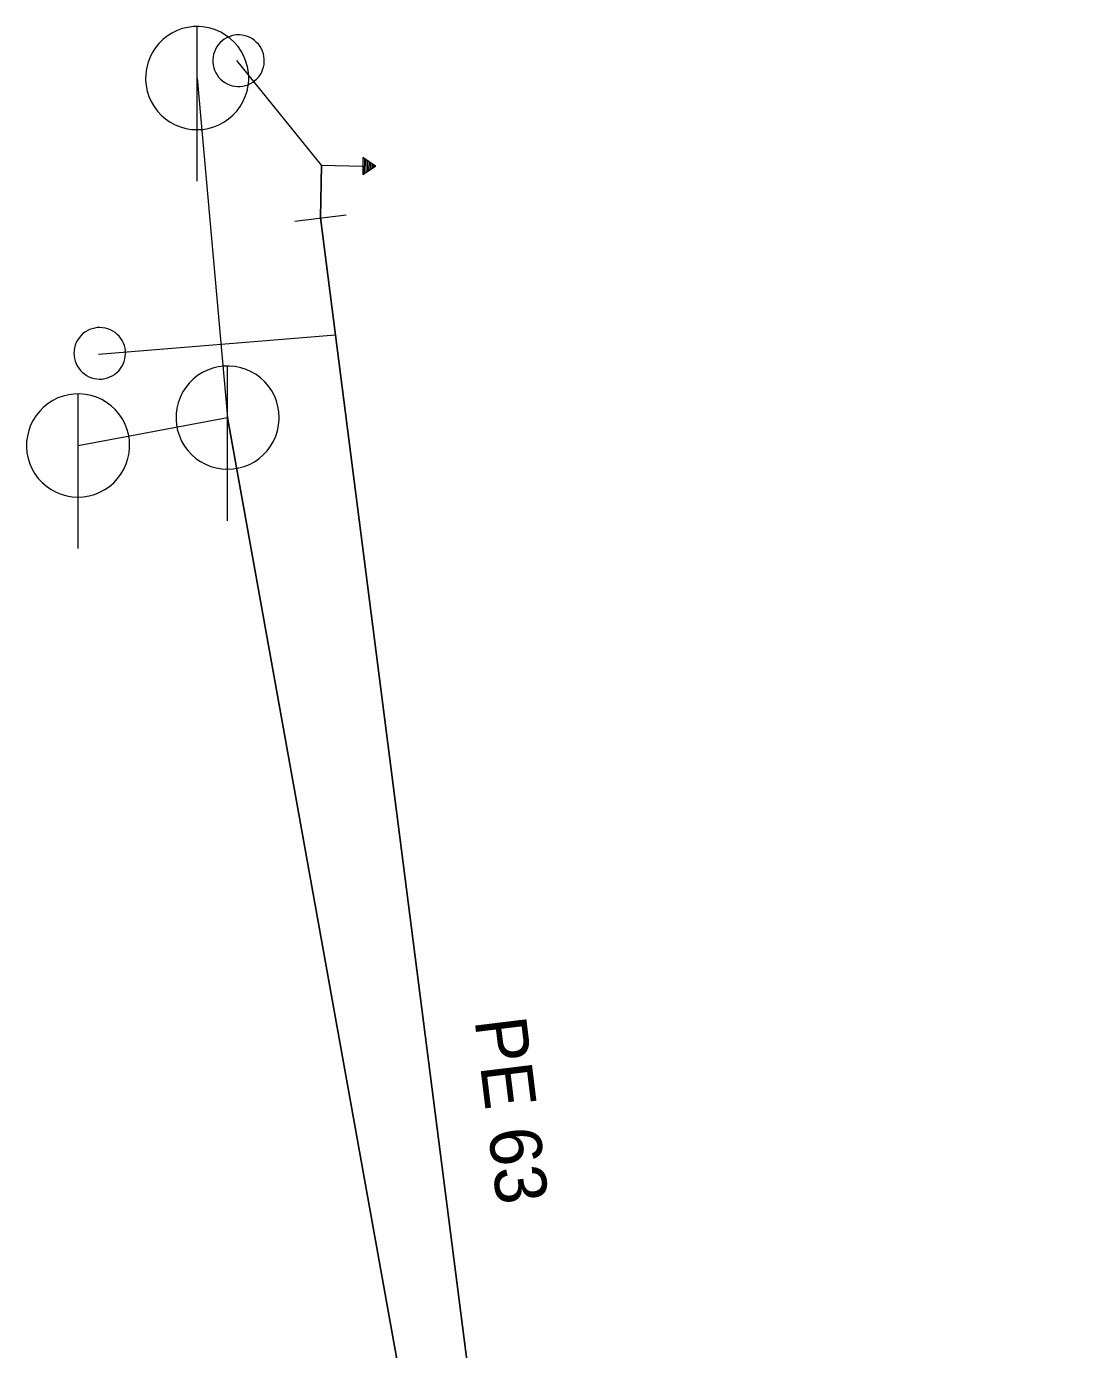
# Model space of a CAD drawing. Extents: x -779496 to -779026, y -977086 to -976624.
# Drawn here: x -779174.9 to -779154.74, y -976726.5 to -976700.86 of the extents above; entities that cross this region are included whole.
import ezdxf

# ---------------------------------------------------------------- set-up
doc = ezdxf.new("R2010")
doc.units = 0
doc.header["$LTSCALE"] = 0.4
doc.linetypes.add('MEDIUM_DASHED', pattern=[4.5, 3, -1.5])
for name, color, linetype, lineweight in [('1', 7, 'MEDIUM_DASHED', 25), ('11', 7, 'Continuous', 13), ('13', 7, 'Continuous', 13), ('14', 7, 'Continuous', 13), ('17', 7, 'Continuous', 25), ('22', 7, 'Continuous', 13), ('23', 7, 'Continuous', 13), ('34', 7, 'Continuous', 13)]:
    doc.layers.add(name, color=color, linetype=linetype, lineweight=lineweight)

msp = doc.modelspace()

# ---------------------------------------------------------------- linework, layer by layer
at = {"layer": '11'}
for p in [(-779171.59, -976701.859), (-779173.899, -976708.98)]:
    msp.add_line(p, (-779171, -976708.44), dxfattribs=at)
at = {"layer": '13'}
for p, q in [((-779169.18, -976703.55), (-779170.82, -976701.52)), ((-779168.91, -976706.84), (-779173.5, -976707.219))]:
    msp.add_line(p, q, dxfattribs=at)
at = {"layer": '14', "lineweight": 25}
msp.add_line((-779171, -976708.44), (-779163.01, -976752.87), dxfattribs=at)
at = {"layer": '17'}
msp.add_lwpolyline([(-779154.739, -976751.5), (-779164.55, -976740.87), (-779168.91, -976706.84), (-779169.199, -976704.57), (-779169.18, -976703.55)], dxfattribs=at)
at = {"layer": '22'}
for p, q in [((-779171.59, -976703.859), (-779171.589, -976700.859)), ((-779171, -976710.44), (-779170.999, -976707.44)), ((-779173.899, -976710.98), (-779173.898, -976707.98))]:
    msp.add_line(p, q, dxfattribs=at)
for points in [[(-779170.59, -976701.859), (-779170.595, -976701.75), (-779170.613, -976701.642), (-779170.643, -976701.536), (-779170.683, -976701.435), (-779170.735, -976701.338), (-779170.797, -976701.248), (-779170.869, -976701.165), (-779170.949, -976701.091), (-779171.037, -976701.025), (-779171.131, -976700.97), (-779171.231, -976700.925), (-779171.336, -976700.892), (-779171.443, -976700.87), (-779171.552, -976700.86), (-779171.662, -976700.862), (-779171.77, -976700.876), (-779171.877, -976700.901), (-779171.98, -976700.938), (-779172.078, -976700.987), (-779172.17, -976701.045), (-779172.256, -976701.114), (-779172.333, -976701.191), (-779172.402, -976701.277), (-779172.461, -976701.369), (-779172.509, -976701.467), (-779172.546, -976701.57), (-779172.572, -976701.677), (-779172.586, -976701.785), (-779172.589, -976701.895), (-779172.579, -976702.004), (-779172.558, -976702.111), (-779172.524, -976702.215), (-779172.48, -976702.315), (-779172.425, -976702.41), (-779172.359, -976702.498), (-779172.285, -976702.578), (-779172.202, -976702.65), (-779172.112, -976702.712), (-779172.016, -976702.764), (-779171.914, -976702.805), (-779171.809, -976702.835), (-779171.701, -976702.853), (-779171.591, -976702.859), (-779171.482, -976702.853), (-779171.374, -976702.835), (-779171.269, -976702.806), (-779171.167, -976702.765), (-779171.07, -976702.713), (-779170.98, -976702.651), (-779170.897, -976702.58), (-779170.822, -976702.5), (-779170.757, -976702.412), (-779170.701, -976702.318), (-779170.657, -976702.218), (-779170.623, -976702.114), (-779170.601, -976702.006), (-779170.591, -976701.897)], [(-779170, -976708.44), (-779170.005, -976708.331), (-779170.023, -976708.223), (-779170.053, -976708.117), (-779170.093, -976708.016), (-779170.145, -976707.919), (-779170.207, -976707.829), (-779170.279, -976707.746), (-779170.359, -976707.672), (-779170.447, -976707.606), (-779170.541, -976707.551), (-779170.641, -976707.506), (-779170.746, -976707.473), (-779170.853, -976707.451), (-779170.962, -976707.441), (-779171.072, -976707.443), (-779171.18, -976707.457), (-779171.287, -976707.482), (-779171.39, -976707.519), (-779171.488, -976707.568), (-779171.58, -976707.626), (-779171.666, -976707.695), (-779171.743, -976707.772), (-779171.812, -976707.858), (-779171.871, -976707.95), (-779171.919, -976708.048), (-779171.956, -976708.151), (-779171.982, -976708.258), (-779171.996, -976708.366), (-779171.999, -976708.476), (-779171.989, -976708.585), (-779171.968, -976708.692), (-779171.934, -976708.796), (-779171.89, -976708.896), (-779171.835, -976708.991), (-779171.769, -976709.079), (-779171.695, -976709.159), (-779171.612, -976709.231), (-779171.522, -976709.293), (-779171.426, -976709.345), (-779171.324, -976709.386), (-779171.219, -976709.416), (-779171.111, -976709.434), (-779171.001, -976709.44), (-779170.892, -976709.434), (-779170.784, -976709.416), (-779170.679, -976709.387), (-779170.577, -976709.346), (-779170.48, -976709.294), (-779170.39, -976709.232), (-779170.307, -976709.161), (-779170.232, -976709.081), (-779170.167, -976708.993), (-779170.111, -976708.899), (-779170.067, -976708.799), (-779170.033, -976708.695), (-779170.011, -976708.587), (-779170.001, -976708.478)], [(-779172.899, -976708.98), (-779172.904, -976708.871), (-779172.922, -976708.763), (-779172.952, -976708.657), (-779172.992, -976708.556), (-779173.044, -976708.459), (-779173.106, -976708.369), (-779173.178, -976708.286), (-779173.258, -976708.212), (-779173.346, -976708.146), (-779173.44, -976708.091), (-779173.54, -976708.046), (-779173.645, -976708.013), (-779173.752, -976707.991), (-779173.861, -976707.981), (-779173.971, -976707.983), (-779174.079, -976707.997), (-779174.186, -976708.022), (-779174.289, -976708.059), (-779174.387, -976708.108), (-779174.479, -976708.166), (-779174.565, -976708.235), (-779174.642, -976708.312), (-779174.711, -976708.398), (-779174.77, -976708.49), (-779174.818, -976708.588), (-779174.855, -976708.691), (-779174.881, -976708.798), (-779174.895, -976708.906), (-779174.898, -976709.016), (-779174.888, -976709.125), (-779174.867, -976709.232), (-779174.833, -976709.336), (-779174.789, -976709.436), (-779174.734, -976709.531), (-779174.668, -976709.619), (-779174.594, -976709.699), (-779174.511, -976709.771), (-779174.421, -976709.833), (-779174.325, -976709.885), (-779174.223, -976709.926), (-779174.118, -976709.956), (-779174.01, -976709.974), (-779173.9, -976709.98), (-779173.791, -976709.974), (-779173.683, -976709.956), (-779173.578, -976709.927), (-779173.476, -976709.886), (-779173.379, -976709.834), (-779173.289, -976709.772), (-779173.206, -976709.701), (-779173.131, -976709.621), (-779173.066, -976709.533), (-779173.01, -976709.439), (-779172.966, -976709.339), (-779172.932, -976709.235), (-779172.91, -976709.127), (-779172.9, -976709.018)]]:
    msp.add_lwpolyline(points, close=True, dxfattribs=at)
at = {"layer": '23'}
for points in [[(-779170.289, -976701.492), (-779170.294, -976701.441), (-779170.306, -976701.389), (-779170.321, -976701.34), (-779170.345, -976701.292), (-779170.371, -976701.247), (-779170.402, -976701.205), (-779170.438, -976701.167), (-779170.476, -976701.132), (-779170.519, -976701.101), (-779170.565, -976701.076), (-779170.613, -976701.055), (-779170.662, -976701.039), (-779170.714, -976701.03), (-779170.766, -976701.024), (-779170.818, -976701.024), (-779170.871, -976701.03), (-779170.922, -976701.042), (-779170.971, -976701.059), (-779171.019, -976701.081), (-779171.063, -976701.107), (-779171.106, -976701.137), (-779171.145, -976701.173), (-779171.18, -976701.213), (-779171.208, -976701.255), (-779171.235, -976701.301), (-779171.255, -976701.348), (-779171.271, -976701.399), (-779171.281, -976701.45), (-779171.286, -976701.502), (-779171.286, -976701.554), (-779171.28, -976701.606), (-779171.269, -976701.658), (-779171.252, -976701.708), (-779171.23, -976701.755), (-779171.204, -976701.799), (-779171.173, -976701.841), (-779171.136, -976701.881), (-779171.099, -976701.915), (-779171.054, -976701.946)], [(-779171.106, -976701.137), (-779171.145, -976701.173), (-779171.18, -976701.213), (-779171.208, -976701.255), (-779171.235, -976701.301), (-779171.255, -976701.348), (-779171.271, -976701.399), (-779171.281, -976701.45), (-779171.286, -976701.502), (-779171.286, -976701.554), (-779171.28, -976701.606), (-779171.269, -976701.658), (-779171.252, -976701.708), (-779171.23, -976701.755), (-779171.204, -976701.799), (-779171.173, -976701.841), (-779171.136, -976701.881), (-779171.099, -976701.915), (-779171.054, -976701.946), (-779171.011, -976701.971), (-779170.963, -976701.992), (-779170.911, -976702.007), (-779170.86, -976702.018), (-779170.807, -976702.022), (-779170.755, -976702.023), (-779170.704, -976702.016), (-779170.652, -976702.004), (-779170.604, -976701.988), (-779170.556, -976701.966), (-779170.511, -976701.939), (-779170.469, -976701.908), (-779170.43, -976701.873), (-779170.395, -976701.834), (-779170.364, -976701.791), (-779170.339, -976701.746), (-779170.32, -976701.698), (-779170.304, -976701.648), (-779170.293, -976701.596), (-779170.288, -976701.544), (-779170.289, -976701.492)], [(-779170.971, -976701.059), (-779171.019, -976701.081), (-779171.063, -976701.107), (-779171.106, -976701.137)], [(-779171.054, -976701.946), (-779171.011, -976701.971), (-779170.963, -976701.992), (-779170.911, -976702.007), (-779170.86, -976702.018), (-779170.807, -976702.022), (-779170.755, -976702.023), (-779170.704, -976702.016), (-779170.652, -976702.004), (-779170.604, -976701.988), (-779170.556, -976701.966), (-779170.511, -976701.939), (-779170.469, -976701.908), (-779170.43, -976701.873), (-779170.395, -976701.834), (-779170.364, -976701.791), (-779170.339, -976701.746), (-779170.32, -976701.698), (-779170.304, -976701.648), (-779170.293, -976701.596), (-779170.288, -976701.544), (-779170.289, -976701.492), (-779170.294, -976701.441), (-779170.306, -976701.389), (-779170.321, -976701.34), (-779170.345, -976701.292), (-779170.371, -976701.247), (-779170.402, -976701.205), (-779170.438, -976701.167), (-779170.476, -976701.132), (-779170.519, -976701.101), (-779170.565, -976701.076), (-779170.613, -976701.055), (-779170.662, -976701.039), (-779170.714, -976701.03), (-779170.766, -976701.024), (-779170.818, -976701.024), (-779170.871, -976701.03), (-779170.922, -976701.042), (-779170.971, -976701.059)], [(-779173.224, -976706.764), (-779173.269, -976706.739), (-779173.319, -976706.72), (-779173.368, -976706.705), (-779173.421, -976706.698), (-779173.473, -976706.695), (-779173.525, -976706.696), (-779173.576, -976706.705), (-779173.627, -976706.717), (-779173.677, -976706.735), (-779173.723, -976706.759), (-779173.768, -976706.787), (-779173.809, -976706.818), (-779173.846, -976706.856), (-779173.879, -976706.895), (-779173.908, -976706.939), (-779173.933, -976706.986), (-779173.952, -976707.035), (-779173.966, -976707.085), (-779173.974, -976707.137), (-779173.978, -976707.188), (-779173.976, -976707.24), (-779173.969, -976707.293), (-779173.956, -976707.344), (-779173.937, -976707.392), (-779173.914, -976707.439), (-779173.886, -976707.483), (-779173.852, -976707.524), (-779173.816, -976707.561), (-779173.776, -976707.594), (-779173.733, -976707.624), (-779173.687, -976707.648), (-779173.638, -976707.668), (-779173.587, -976707.682), (-779173.536, -976707.691), (-779173.484, -976707.693), (-779173.432, -976707.692), (-779173.379, -976707.684), (-779173.33, -976707.672), (-779173.279, -976707.652)], [(-779173.976, -976707.24), (-779173.969, -976707.293), (-779173.956, -976707.344), (-779173.937, -976707.392), (-779173.914, -976707.439), (-779173.886, -976707.483), (-779173.852, -976707.524), (-779173.816, -976707.561), (-779173.776, -976707.594), (-779173.733, -976707.624), (-779173.687, -976707.648), (-779173.638, -976707.668), (-779173.587, -976707.682), (-779173.536, -976707.691), (-779173.484, -976707.693), (-779173.432, -976707.692), (-779173.379, -976707.684), (-779173.33, -976707.672), (-779173.279, -976707.652), (-779173.234, -976707.63), (-779173.189, -976707.603), (-779173.147, -976707.568), (-779173.11, -976707.532), (-779173.077, -976707.491), (-779173.047, -976707.448), (-779173.024, -976707.402), (-779173.005, -976707.353), (-779172.991, -976707.303), (-779172.982, -976707.251), (-779172.979, -976707.199), (-779172.981, -976707.147), (-779172.988, -976707.095), (-779173.001, -976707.044), (-779173.019, -976706.995), (-779173.042, -976706.948), (-779173.071, -976706.906), (-779173.103, -976706.864), (-779173.14, -976706.826), (-779173.181, -976706.792), (-779173.224, -976706.764)], [(-779173.279, -976707.652), (-779173.234, -976707.63), (-779173.189, -976707.603), (-779173.147, -976707.568), (-779173.11, -976707.532), (-779173.077, -976707.491), (-779173.047, -976707.448), (-779173.024, -976707.402), (-779173.005, -976707.353), (-779172.991, -976707.303), (-779172.982, -976707.251), (-779172.979, -976707.199), (-779172.981, -976707.147), (-779172.988, -976707.095), (-779173.001, -976707.044), (-779173.019, -976706.995), (-779173.042, -976706.948), (-779173.071, -976706.906), (-779173.103, -976706.864), (-779173.14, -976706.826), (-779173.181, -976706.792), (-779173.224, -976706.764), (-779173.269, -976706.739), (-779173.319, -976706.72), (-779173.368, -976706.705), (-779173.421, -976706.698), (-779173.473, -976706.695), (-779173.525, -976706.696), (-779173.576, -976706.705), (-779173.627, -976706.717), (-779173.677, -976706.735), (-779173.723, -976706.759), (-779173.768, -976706.787), (-779173.809, -976706.818), (-779173.846, -976706.856), (-779173.879, -976706.895), (-779173.908, -976706.939), (-779173.933, -976706.986), (-779173.952, -976707.035), (-779173.966, -976707.085)], [(-779173.966, -976707.085), (-779173.974, -976707.137), (-779173.978, -976707.188), (-779173.976, -976707.24)]]:
    msp.add_lwpolyline(points, dxfattribs=at)
at = {"layer": '34'}
for p, q in [((-779168.348, -976703.42), (-779168.35, -976703.711)), ((-779168.319, -976703.44), (-779168.32, -976703.691)), ((-779168.288, -976703.461), (-779168.29, -976703.672)), ((-779168.258, -976703.482), (-779168.26, -976703.652)), ((-779168.229, -976703.501), (-779168.229, -976703.632)), ((-779169.179, -976703.55), (-779168.379, -976703.565)), ((-779168.199, -976703.522), (-779168.199, -976703.613)), ((-779168.169, -976703.542), (-779168.17, -976703.593)), ((-779168.139, -976703.563), (-779168.139, -976703.573)), ((-779169.694, -976704.633), (-779168.702, -976704.507))]:
    msp.add_line(p, q, dxfattribs=at)
msp.add_lwpolyline([(-779168.38, -976703.731), (-779168.131, -976703.568), (-779168.378, -976703.4)], close=True, dxfattribs=at)

# ---------------------------------------------------------------- texts
at = {"layer": '1'}
msp.add_text('PE 63 ', height=1, rotation=277, dxfattribs=at).set_placement((-779166.214, -976720.114))

doc.saveas('drawing.dxf')
